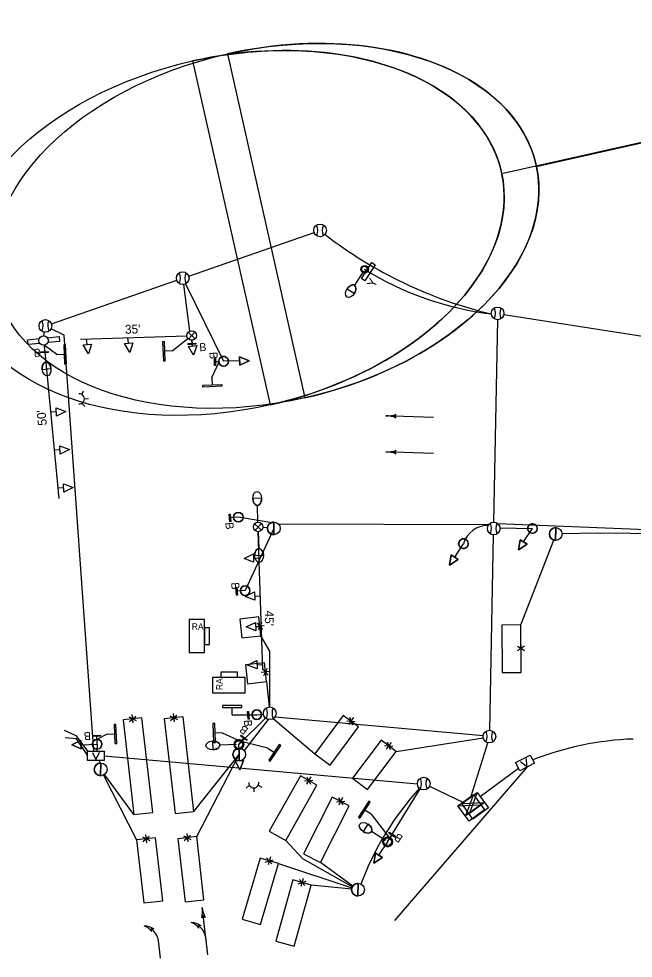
# Model space of a CAD drawing. Extents: x 596176 to 605330, y 332416 to 402398.
# Drawn here: x 604308.1 to 604501.7, y 339230.9 to 339526.7 of the extents above; entities that cross this region are included whole.
import ezdxf

# ---------------------------------------------------------------- set-up
doc = ezdxf.new("R2010")
doc.units = 0
for name, color, linetype in [('P_LTG', 7, 'Continuous'), ('P_SIG', 7, 'Continuous'), ('P_SIG_Bold', 7, 'Continuous'), ('P_SIG_Conduit', 7, 'Continuous'), ('P_SIG_IC', 7, 'Continuous'), ('P_SIG_Loops', 7, 'Continuous')]:
    doc.layers.add(name, color=color, linetype=linetype)

# ---------------------------------------------------------------- blocks, each defined once
blk = doc.blocks.new('_U317')
at = {"layer": 'P_LTG'}
for p, q in [((4.32, 25.12), (-4.14, 25.12)), ((0.05, 2.3), (0.05, 18.44))]:
    blk.add_line(p, q, dxfattribs=at)
blk.add_circle((0.05, 0.15), 3.68, dxfattribs=at)
blk.add_ellipse((0.09, 25.12), major_axis=(0, 6.65), ratio=0.636439, dxfattribs=at)
blk.add_ellipse((0.09, 25.12), major_axis=(0, 6.65), ratio=0.636439, start_param=1.570796, end_param=4.712389, dxfattribs=at)
blk = doc.blocks.new('_U318')
at = {"layer": 'P_LTG'}
for p, q in [((4.323, 25.117), (-4.138, 25.117)), ((0.048, 2.299), (0.048, 18.436))]:
    blk.add_line(p, q, dxfattribs=at)
blk.add_ellipse((0.092, 25.117), major_axis=(0, 6.647), ratio=0.636439, dxfattribs=at)
blk.add_ellipse((0.092, 25.117), major_axis=(0, 6.647), ratio=0.636439, start_param=1.570796, end_param=4.712389, dxfattribs=at)
blk = doc.blocks.new('_U226')
at = {"layer": 'P_SIG'}
blk.add_line((0.03, 6.11), (-0.03, -6.09), dxfattribs=at)
blk.add_lwpolyline([(-0.03, -6.09), (0.03, 6.11)], dxfattribs=at)
blk.add_circle((0, 0.01), 6.1, dxfattribs=at)
for start, end in [(89.70079, 180), (180, 269.70079)]:
    blk.add_arc((0, 0.01), 6.1, start, end, dxfattribs=at)
blk = doc.blocks.new('_U307')
at = {"layer": 'P_SIG_Loops'}
for p, q in [((0, 0), (0, -0.229)), ((0.517, -0.313), (0.624, -0.147)), ((0.627, -0.312), (0.518, -0.146)), ((0.467, -0.23), (0.671, -0.23))]:
    blk.add_line(p, q, dxfattribs=at)
blk.add_lwpolyline([(0, -0.229), (1.143, -0.229), (1.143, 0.229), (0, 0.229)], close=True, dxfattribs=at)
blk = doc.blocks.new('CONTROL CABINET_2')
at = {"layer": 'P_SIG'}
for p, q in [((-0.229, 0.305), (0.229, 0.305)), ((-0.229, -0.152), (-0.229, 0.305)), ((0.229, 0.305), (0.229, -0.152)), ((-0.229, 0.152), (0.229, 0.152)), ((-0.229, -0.152), (0.229, 0.152)), ((0.229, -0.152), (-0.229, 0.152)), ((0.229, -0.152), (-0.229, -0.152))]:
    blk.add_line(p, q, dxfattribs=at)
blk = doc.blocks.new('COMMUNICATION VAULT')
at = {"layer": 'P_SIG'}
for p in [(-1.61, 1.65), (1.56, 1.65)]:
    blk.add_line(p, (-0.03, -1.65), dxfattribs=at)
blk.add_lwpolyline([(-3.98, 2.22), (3.98, 2.22), (3.98, -2.22), (-3.98, -2.22)], close=True, dxfattribs=at)

msp = doc.modelspace()

# ---------------------------------------------------------------- linework, layer by layer
at = {"layer": 'P_SIG'}
for p, q in [((604416.11, 339444.89), (604419.37, 339449.93)), ((604420.38, 339449.28), (604417.11, 339444.24)), ((604419.37, 339449.93), (604420.38, 339449.28)), ((604417.11, 339444.24), (604416.11, 339444.89)), ((604329.66, 339424.14), (604329.45, 339425.9)), ((604342.7, 339424.56), (604342.49, 339426.32)), ((604356.38, 339422.11), (604361.38, 339426.04)), ((604362.84, 339423.71), (604362.63, 339425.47)), ((604362.63, 339425.46), (604362.67, 339424.47)), ((604316.05, 339423.89), (604316.14, 339421.91)), ((604320.12, 339420.97), (604316.11, 339423.9)), ((604356.38, 339422.11), (604353.98, 339422)), ((604320.12, 339420.97), (604322.52, 339421.08)), ((604368.88, 339413.72), (604371.27, 339418.66)), ((604371.1, 339418.7), (604370.1, 339418.68)), ((604377.67, 339418.96), (604372.61, 339418.86)), ((604368.88, 339413.72), (604368.99, 339411.32)), ((604327.93, 339408.43), (604328.5, 339409.52)), ((604328.77, 339407.07), (604330, 339407.09)), ((604327.95, 339405.64), (604328.85, 339404.67)), ((604319.9, 339402.91), (604318.13, 339402.86)), ((604438.73, 339401.16), (604426.17, 339401.61)), ((604321.06, 339390.95), (604319.29, 339390.89)), ((604438.73, 339389.81), (604426.17, 339390.25)), ((604322.22, 339378.98), (604320.45, 339378.92)), ((604377.27, 339369.77), (604374.78, 339369.56)), ((604388.46, 339368.23), (604388.44, 339364.23)), ((604467.17, 339361.96), (604469.95, 339366.19)), ((604445.44, 339357.18), (604448.21, 339361.41)), ((604382.04, 339356.89), (604383.81, 339356.94)), ((604379.42, 339346.64), (604376.92, 339346.44)), ((604382.43, 339344.89), (604384.2, 339344.95)), ((604382.73, 339335.32), (604384.5, 339335.37)), ((604383.1, 339323.28), (604384.87, 339323.34)), ((604375.28, 339307.56), (604375.28, 339309.96)), ((604375.28, 339307.56), (604383.08, 339307.56)), ((604383.08, 339307.56), (604380.59, 339307.36)), ((604332.78, 339298.24), (604332.64, 339300.73)), ((604335.97, 339301.38), (604332.69, 339299.78)), ((604335.97, 339301.38), (604338.37, 339301.5)), ((604372.22, 339301.9), (604369.82, 339301.79)), ((604372.22, 339301.9), (604378.2, 339299.14)), ((604377.45, 339298.14), (604378.95, 339300.14)), ((604327.72, 339298.12), (604332.78, 339298.26)), ((604377.6, 339293.11), (604377.45, 339298.16)), ((604386.61, 339296.99), (604378.2, 339299.14)), ((604331.31, 339295.67), (604332.35, 339293.5)), ((604333.39, 339295.67), (604332.35, 339293.5)), ((604377.55, 339297.03), (604377.53, 339293.03)), ((604386.61, 339296.99), (604388.62, 339295.68)), ((604333.9, 339292.32), (604333.88, 339288.32)), ((604380.75, 339285.33), (604379.78, 339284.43)), ((604383.54, 339285.35), (604384.63, 339284.78)), ((604382.18, 339284.51), (604382.2, 339283.28)), ((604446.48, 339278.91), (604451.34, 339282.43)), ((604451.34, 339282.43), (604448.82, 339275.67)), ((604451.34, 339282.43), (604454.86, 339277.57)), ((604419.11, 339276.2), (604417.09, 339277.5)), ((604446.48, 339278.91), (604453.68, 339279.19)), ((604450, 339274.06), (604446.48, 339278.91)), ((604453.68, 339279.19), (604448.82, 339275.67)), ((604454.86, 339277.57), (604450, 339274.06)), ((604419.11, 339276.2), (604425.02, 339268.54)), ((604421.56, 339263.29), (604424.34, 339267.52)), ((604424.32, 339267.5), (604425.71, 339269.58)), ((604414.98, 339254.42), (604414.96, 339250.42)), ((604367.62, 339231.98), (604366.17, 339244.46)), ((604364.87, 339240.35), (604364.59, 339241.22)), ((604365.55, 339241.09), (604364.59, 339241.22)), ((604350.03, 339239.26), (604349.75, 339240.12)), ((604350.71, 339239.99), (604349.75, 339240.12)), ((604352.78, 339230.88), (604352.13, 339236.43)), ((604367.62, 339231.98), (604366.98, 339237.53))]:
    msp.add_line(p, q, dxfattribs=at)
for points in [[(604419.37, 339449.93), (604420.38, 339449.28), (604417.11, 339444.24), (604416.11, 339444.89)], [(604330.01, 339421.21), (604328.36, 339423.99), (604330.97, 339424.3)], [(604343.05, 339421.62), (604341.4, 339424.41), (604344.01, 339424.72)], [(604354.25, 339419.05), (604353.97, 339425.04), (604353.37, 339425.01), (604353.65, 339419.02)], [(604361.47, 339424.41), (604363.87, 339424.52), (604363.89, 339424.2), (604361.49, 339424.09)], [(604314.94, 339421.86), (604317.34, 339421.97), (604317.35, 339421.64), (604314.95, 339421.53)], [(604322.24, 339424.03), (604322.52, 339418.03), (604323.12, 339418.06), (604322.84, 339424.06)], [(604363.19, 339420.77), (604361.53, 339423.55), (604364.14, 339423.86)], [(604370.08, 339419.88), (604370.12, 339417.48), (604369.8, 339417.48), (604369.76, 339419.88)], [(604366.03, 339411.32), (604372.03, 339411.59), (604372.05, 339410.99), (604366.06, 339410.72)], [(604322.86, 339403.01), (604319.94, 339401.6), (604319.86, 339404.23)], [(604324.02, 339391.04), (604321.1, 339389.63), (604321.02, 339392.26)], [(604325.17, 339379.07), (604322.26, 339377.66), (604322.17, 339380.29)], [(604374.68, 339370.76), (604374.88, 339368.37), (604374.56, 339368.34), (604374.36, 339370.73)], [(604379.09, 339356.79), (604382, 339358.2), (604382.08, 339355.57)], [(604376.83, 339347.63), (604377.02, 339345.24), (604376.7, 339345.22), (604376.5, 339347.61)], [(604379.47, 339344.8), (604382.39, 339346.21), (604382.47, 339343.58)], [(604366.6, 339327.17), (604366.6, 339337.52), (604361.78, 339337.52), (604361.78, 339327.17)], [(604379.78, 339335.22), (604382.69, 339336.63), (604382.78, 339334)], [(604368.23, 339334.89), (604366.63, 339334.89), (604366.63, 339329.62), (604368.23, 339329.62)], [(604380.15, 339323.19), (604383.06, 339324.6), (604383.15, 339321.97)], [(604371.72, 339320.95), (604371.72, 339319.35), (604376.99, 339319.35), (604376.99, 339320.95)], [(604379.44, 339319.32), (604369.09, 339319.32), (604369.09, 339314.5), (604379.44, 339314.5)], [(604372.32, 339309.83), (604378.32, 339309.83), (604378.32, 339310.43), (604372.32, 339310.43)], [(604380.49, 339308.55), (604380.69, 339306.16), (604380.36, 339306.13), (604380.16, 339308.53)], [(604338.1, 339304.44), (604338.38, 339298.45), (604338.98, 339298.48), (604338.7, 339304.47)], [(604370.09, 339298.84), (604369.82, 339304.84), (604369.22, 339304.81), (604369.49, 339298.81)], [(604333.84, 339300.8), (604331.44, 339300.67), (604331.42, 339300.99), (604333.82, 339301.13)], [(604379.91, 339299.43), (604377.99, 339300.86), (604378.18, 339301.12), (604380.1, 339299.69)], [(604390.12, 339298.23), (604386.84, 339293.2), (604387.34, 339292.88), (604390.62, 339297.9)], [(604329.76, 339296.04), (604334.97, 339296.04), (604334.97, 339293.13), (604329.76, 339293.13)], [(604415.6, 339274.94), (604418.86, 339279.98), (604418.35, 339280.31), (604415.1, 339275.27)], [(604426.71, 339268.92), (604424.71, 339270.25), (604424.89, 339270.52), (604426.89, 339269.19)]]:
    msp.add_lwpolyline(points, close=True, dxfattribs=at)
for points in [[(604380.63, 339419.02), (604377.7, 339417.64), (604377.64, 339420.28), (604380.63, 339419.02)], [(604377.7, 339417.64), (604380.63, 339419.02), (604377.64, 339420.28), (604377.7, 339417.64)], [(604426.98, 339402.08), (604426.17, 339401.61), (604426.95, 339401.08)], [(604426.98, 339390.72), (604426.17, 339390.25), (604426.95, 339389.73)], [(604388.44, 339364.23), (604388.46, 339368.23)], [(604465.55, 339359.49), (604466.07, 339362.68), (604468.27, 339361.24), (604465.55, 339359.49)], [(604466.07, 339362.68), (604465.55, 339359.49), (604468.27, 339361.24), (604466.07, 339362.68)], [(604443.82, 339354.7), (604444.33, 339357.9), (604446.54, 339356.46), (604443.82, 339354.7)], [(604444.33, 339357.9), (604443.82, 339354.7), (604446.54, 339356.46), (604444.33, 339357.9)], [(604324.76, 339298.03), (604327.68, 339299.43), (604327.76, 339296.8), (604324.76, 339298.03)], [(604327.68, 339299.43), (604324.76, 339298.03), (604327.76, 339296.8), (604327.68, 339299.43)], [(604377.53, 339293.03), (604377.55, 339297.03)], [(604333.88, 339288.32), (604333.9, 339292.32)], [(604377.69, 339290.15), (604376.28, 339293.07), (604378.92, 339293.15), (604377.69, 339290.15)], [(604376.28, 339293.07), (604377.69, 339290.15), (604378.92, 339293.15), (604376.28, 339293.07)], [(604419.94, 339260.82), (604420.46, 339264.01), (604422.66, 339262.57), (604419.94, 339260.82)], [(604420.46, 339264.01), (604419.94, 339260.82), (604422.66, 339262.57), (604420.46, 339264.01)], [(604414.96, 339250.42), (604414.98, 339254.42)], [(604366.76, 339243.73), (604366.17, 339244.46), (604365.77, 339243.61)]]:
    msp.add_lwpolyline(points, dxfattribs=at)
for centre, radius in [((604403.02, 339460.06), 2), ((604416.98, 339447.88), 0.9), ((604359.75, 339445.03), 2), ((604458.96, 339433.95), 2), ((604316.49, 339430), 2), ((604372.61, 339418.86), 1.52), ((604372.61, 339418.86), 1.52), ((604372.61, 339418.86), 1.52), ((604377.27, 339369.77), 1.52), ((604388.45, 339366.23), 2), ((604457.74, 339366.2), 2), ((604469.95, 339366.19), 1.52), ((604469.95, 339366.19), 1.52), ((604469.95, 339366.19), 1.52), ((604448.21, 339361.41), 1.52), ((604448.21, 339361.41), 1.52), ((604448.21, 339361.41), 1.52), ((604379.42, 339346.64), 1.52), ((604383.08, 339307.56), 1.52), ((604387.17, 339308.02), 2), ((604456.37, 339300.69), 2), ((604332.78, 339298.26), 1.52), ((604332.78, 339298.26), 1.52), ((604332.78, 339298.26), 1.52), ((604377.45, 339298.16), 1.52), ((604377.45, 339298.16), 1.52), ((604377.45, 339298.16), 1.52), ((604377.54, 339295.03), 2), ((604333.89, 339290.32), 2), ((604435.69, 339285.86), 2), ((604424.34, 339267.52), 1.52), ((604424.34, 339267.52), 1.52), ((604424.34, 339267.52), 1.52), ((604414.97, 339252.42), 2)]:
    msp.add_circle(centre, radius, dxfattribs=at)
for centre, radius, start, end in [((604397.95, 339460.09), 4.36, 336.6741, 22.5272), ((604408.09, 339460.1), 4.36, 157.5751, 203.4282), ((604354.68, 339445.06), 4.36, 336.6741, 22.5272), ((604364.82, 339445.07), 4.36, 157.5751, 203.4282), ((604453.89, 339433.98), 4.36, 336.6741, 22.5272), ((604464.03, 339433.99), 4.36, 157.5751, 203.4282), ((604311.42, 339430.03), 4.36, 336.6741, 22.5272), ((604321.56, 339430.04), 4.36, 157.5751, 203.4282), ((604372.61, 339418.86), 1.52, 1.2579, 181.2579), ((604372.61, 339418.86), 1.52, 181.2579, 1.2579), ((604327.2, 339407.03), 1.58, 263.3712, 98.8787), ((604424.14, 339412.17), 10.49, 267.9585, 285.7208), ((604423.39, 339391.21), 10.49, 70.1962, 87.9585), ((604424.14, 339400.82), 10.49, 267.9585, 285.7208), ((604423.39, 339379.86), 10.49, 70.1962, 87.9585), ((604377.27, 339369.77), 1.52, 0, 180), ((604377.27, 339369.77), 1.52, 180, 0), ((604388.45, 339366.23), 2, 89.7008, 180), ((604388.45, 339366.23), 2, 180, 269.7008), ((604452.67, 339366.23), 4.36, 336.6741, 22.5272), ((604462.81, 339366.24), 4.36, 157.5751, 203.4282), ((604469.95, 339366.19), 1.52, 56.8293, 236.8293), ((604469.95, 339366.19), 1.52, 236.8293, 56.8293), ((604448.21, 339361.41), 1.52, 56.8293, 236.8293), ((604448.21, 339361.41), 1.52, 236.8293, 56.8293), ((604379.42, 339346.64), 1.52, 0, 180), ((604379.42, 339346.64), 1.52, 180, 0), ((604383.08, 339307.56), 1.52, 0, 180), ((604382.1, 339308.06), 4.36, 336.6741, 22.5272), ((604392.24, 339308.07), 4.36, 157.5751, 203.4282), ((604383.08, 339307.56), 1.52, 180, 0), ((604451.3, 339300.73), 4.36, 336.6741, 22.5272), ((604461.44, 339300.74), 4.36, 157.5751, 203.4282), ((604332.78, 339298.26), 1.52, 1.8031, 181.8031), ((604332.78, 339298.26), 1.52, 181.8031, 1.8031), ((604377.45, 339298.16), 1.52, 91.8031, 271.8031), ((604377.45, 339298.16), 1.52, 271.8031, 91.8031), ((604377.54, 339295.03), 2, 89.7008, 180), ((604377.54, 339295.03), 2, 180, 269.7008), ((604333.89, 339290.32), 2, 89.7008, 180), ((604333.89, 339290.32), 2, 180, 269.7008), ((604382.14, 339286.08), 1.58, 173.3712, 8.8787), ((604430.62, 339285.9), 4.36, 336.6741, 22.5272), ((604440.76, 339285.9), 4.36, 157.5751, 203.4282), ((604424.34, 339267.52), 1.52, 56.8293, 236.8293), ((604424.34, 339267.52), 1.52, 236.8293, 56.8293), ((604414.97, 339252.42), 2, 89.7008, 180), ((604414.97, 339252.42), 2, 180, 269.7008), ((604355.48, 339245.64), 10.49, 348.8556, 6.6179), ((604376.32, 339248.06), 10.49, 186.6179, 204.3803), ((604345.91, 339236.18), 5.14, 36.7028, 71.3512), ((604347.27, 339234.99), 6.07, 55.4464, 87.3026), ((604360.75, 339237.28), 5.14, 36.7028, 71.3512), ((604362.11, 339236.09), 6.07, 55.4464, 87.3026), ((604361.28, 339236.46), 5.8, 10.5832, 55.1471), ((604346.43, 339235.37), 5.8, 10.5832, 55.1471)]:
    msp.add_arc(centre, radius, start, end, dxfattribs=at)
at = {"layer": 'P_SIG_Bold'}
for p, q in [((604361.46, 339427.99), (604363.65, 339425.94)), ((604363.58, 339428.06), (604361.53, 339425.87)), ((604327.58, 339425.84), (604361.06, 339426.92)), ((604316.05, 339423.89), (604320.71, 339375.62)), ((604382.4, 339367.72), (604384.59, 339365.66)), ((604382.47, 339365.6), (604384.52, 339367.78)), ((604384.94, 339321.71), (604383.55, 339365.19))]:
    msp.add_line(p, q, dxfattribs=at)
for points in [[(604314.68, 339424.51), (604311, 339424.16), (604310.85, 339425.65), (604314.54, 339426.01)], [(604317.12, 339426.26), (604320.81, 339426.61), (604320.95, 339425.12), (604317.27, 339424.76)]]:
    msp.add_lwpolyline(points, dxfattribs=at)
for centre in [(604362.56, 339426.96), (604315.9, 339425.39), (604383.5, 339366.69)]:
    msp.add_circle(centre, 1.5, dxfattribs=at)
at = {"layer": 'P_SIG_Conduit'}
for p, q in [((604360.01, 339443.04), (604361.88, 339428.3)), ((604360.64, 339443.23), (604372.61, 339418.86)), ((604458.92, 339431.95), (604457.68, 339368.2)), ((604316, 339426.88), (604316.17, 339428.02)), ((604388.46, 339367.86), (604377.27, 339369.77)), ((604388.45, 339366.23), (604379.42, 339346.64)), ((604459, 339367.75), (604540.44, 339364.59)), ((604457.61, 339364.2), (604456.41, 339302.69)), ((604377.45, 339298.19), (604385.87, 339306.5)), ((604386.65, 339306.09), (604379.11, 339296.27)), ((604383.08, 339307.56), (604385.19, 339307.74)), ((604332.78, 339298.26), (604332.71, 339296.04)), ((604450.64, 339281.93), (604455.87, 339298.75)), ((604334.97, 339294.58), (604433.69, 339285.83)), ((604333.56, 339293.13), (604333.65, 339292.31)), ((604437.5, 339285.01), (604448.02, 339280.03))]:
    msp.add_line(p, q, dxfattribs=at)
for points in [[(604361.64, 339445.68), (604401.13, 339459.4)], [(604318.38, 339430.65), (604357.87, 339444.37)], [(604460.93, 339433.64), (604522.77, 339423.92)], [(604331.69, 339296.04), (604322.39, 339427.06), (604318.27, 339429.09)], [(604386.46, 339366.41), (604384.99, 339366.55)], [(604389.89, 339367.62), (604456.16, 339367.43)], [(604459.73, 339366.42), (604469.95, 339366.19)], [(604632.71, 339363.27), (604490.54, 339364.68), (604479.27, 339364.49)], [(604388.85, 339306.94), (604454.4, 339301)], [(604322.43, 339302.71), (604326.09, 339301.02), (604329.69, 339296.04)], [(604329.69, 339294.79), (604326.31, 339299.98), (604322.71, 339300.31)], [(604424.32, 339267.5), (604434.61, 339284.18)]]:
    msp.add_lwpolyline(points, dxfattribs=at)
for centre, radius, start, end in [((604489.18, 339568.4), 138.44, 232.3316, 256.5435), ((604468.99, 339531.6), 98.57, 238.1454, 262.9944), ((604455.92, 339359.13), 8.04, 89.5224, 163.5022), ((604504.2, 339220.92), 94.4, 137.747, 159.353)]:
    msp.add_arc(centre, radius, start, end, dxfattribs=at)
at = {"layer": 'P_SIG_IC'}
msp.add_line((604426.58, 339242.71), (604468.43, 339291.17), dxfattribs=at)
msp.add_lwpolyline([(604453.47, 339281.83), (604465.51, 339290.72)], dxfattribs=at)
msp.add_arc((604504.95, 339205.09), 94.87, 91.963, 111.5856, dxfattribs=at)
at = {"layer": 'P_SIG_Loops'}
for p, q in [((604466.26, 339335.87), (604476.72, 339362.54)), ((604385.4, 339335.56), (604382.74, 339335.25)), ((604383.18, 339336.39), (604384.85, 339334.39)), ((604384.63, 339336.56), (604383.47, 339334.24)), ((604384.04, 339335.38), (604383.7, 339338.36)), ((604385.8, 339320.95), (604385.46, 339323.93)), ((604387.17, 339321.12), (604384.5, 339320.82)), ((604384.95, 339321.95), (604386.62, 339319.96)), ((604386.39, 339322.13), (604385.24, 339319.81)), ((604343.93, 339306.25), (604340.95, 339305.91)), ((604342.75, 339306.84), (604345.07, 339305.69)), ((604342.92, 339305.4), (604344.92, 339307.06)), ((604343.75, 339307.61), (604344.06, 339304.95)), ((604356.91, 339306.59), (604353.93, 339306.25)), ((604355.73, 339307.18), (604358.05, 339306.03)), ((604355.91, 339305.73), (604357.9, 339307.4)), ((604356.74, 339307.95), (604357.04, 339305.29)), ((604388.24, 339306.34), (604401.41, 339295.28)), ((604412.75, 339305.55), (604410.34, 339307.33)), ((604413.55, 339306.66), (604411.96, 339304.51)), ((604412.29, 339306.78), (604413.2, 339304.36)), ((604411.44, 339305.61), (604414.03, 339305.47)), ((604427.04, 339295.94), (604454.42, 339300.25)), ((604424.65, 339297.76), (604422.26, 339299.57)), ((604423.34, 339297.83), (604425.93, 339297.66)), ((604425.47, 339298.86), (604423.85, 339296.73)), ((604424.21, 339299), (604425.09, 339296.56)), ((604363.29, 339277.12), (604377.54, 339295.03)), ((604364.17, 339269.17), (604377.54, 339295.03)), ((604334.8, 339288.54), (604345.23, 339268.15)), ((604344.35, 339276.1), (604335.07, 339288.71)), ((604399.43, 339286.83), (604396.81, 339288.3)), ((604398.12, 339286.72), (604400.71, 339286.91)), ((604400.08, 339288.03), (604398.77, 339285.7)), ((604398.82, 339288), (604400.02, 339285.7)), ((604409.52, 339280.24), (604406.84, 339281.59)), ((604408.21, 339280.08), (604410.8, 339280.38)), ((604408.86, 339281.38), (604410.16, 339279.14)), ((604410.12, 339281.47), (604408.92, 339279.08)), ((604348.21, 339268.49), (604345.23, 339268.15)), ((604347.03, 339269.08), (604349.35, 339267.93)), ((604347.2, 339267.64), (604349.2, 339269.31)), ((604348.03, 339269.85), (604348.34, 339267.19)), ((604361.19, 339268.83), (604358.21, 339268.49)), ((604360.01, 339269.42), (604362.33, 339268.27)), ((604360.19, 339267.98), (604362.19, 339269.64)), ((604361.02, 339270.19), (604361.32, 339267.53)), ((604387.01, 339261.51), (604384.13, 339262.36)), ((604385.75, 339261.12), (604388.24, 339261.87)), ((604386.15, 339262.51), (604387.84, 339260.55)), ((604387.38, 339262.83), (604386.62, 339260.26)), ((604413.36, 339253.6), (604403.18, 339261.04)), ((604396.5, 339255.7), (604398.21, 339253.75)), ((604397.72, 339256.03), (604397, 339253.45)), ((604397.37, 339254.71), (604394.48, 339255.51)), ((604396.12, 339254.29), (604398.6, 339255.09)), ((604412.98, 339252.62), (604400.26, 339253.9))]:
    msp.add_line(p, q, dxfattribs=at)
for points in [[(604383.7, 339338.36), (604377.73, 339337.68), (604378.42, 339331.72), (604384.38, 339332.4)], [(604385.46, 339323.93), (604379.5, 339323.25), (604380.18, 339317.29), (604386.14, 339317.97)], [(604340.95, 339305.91), (604344.35, 339276.1), (604350.31, 339276.78), (604346.91, 339306.59)], [(604353.93, 339306.25), (604357.33, 339276.44), (604363.29, 339277.12), (604359.89, 339306.93)], [(604410.34, 339307.33), (604401.41, 339295.28), (604406.23, 339291.71), (604415.16, 339303.76)], [(604422.26, 339299.57), (604413.2, 339287.61), (604417.98, 339283.99), (604427.04, 339295.94)], [(604396.81, 339288.3), (604387.01, 339270.86), (604392.24, 339267.92), (604402.04, 339285.36)], [(604406.84, 339281.59), (604397.82, 339263.74), (604403.18, 339261.04), (604412.2, 339278.89)], [(604345.23, 339268.15), (604347.49, 339248.28), (604353.46, 339248.96), (604351.19, 339268.83)], [(604358.21, 339268.49), (604360.48, 339248.62), (604366.44, 339249.3), (604364.17, 339269.17)], [(604384.13, 339262.36), (604378.48, 339243.18), (604384.23, 339241.48), (604389.89, 339260.66)], [(604394.48, 339255.51), (604389.09, 339236.25), (604394.87, 339234.64), (604400.26, 339253.9)]]:
    msp.add_lwpolyline(points, close=True, dxfattribs=at)
for points in [[(604387.17, 339310.02), (604387.16, 339327.57), (604384.38, 339332.4)], [(604386.14, 339317.97), (604386.96, 339310.01)], [(604392.24, 339267.92), (604397.46, 339262.3), (604413.23, 339253.4)], [(604389.89, 339260.66), (604413.07, 339253.04)]]:
    msp.add_lwpolyline(points, dxfattribs=at)

# ---------------------------------------------------------------- block references
at = {"layer": 'P_SIG'}
for name, p, xscale, yscale, rotation in [('_U318', (604707.83, 339532.72), 13.123333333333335, 13.123333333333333, 102.6891845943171), ('_U318', (604696.9, 339530.5), 13.123333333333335, 13.123333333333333, 102.6891845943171), ('_U317', (604417.13, 339447.88), 0.32808333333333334, 0.32808333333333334, 147.58059147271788), ('_U318', (604315.98, 339424.64), 0.32808333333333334, 0.32808333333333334, -173.71516295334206), ('_U318', (604383.46, 339367.43), 0.32808333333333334, 0.3280833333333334, 1.956191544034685), ('_U318', (604383.54, 339365.94), 0.3280833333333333, 0.32808333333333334, -178.0438084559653), ('_U317', (604377.45, 339298.16), 0.32808333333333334, 0.32808333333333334, 91.9352759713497), ('CONTROL CABINET_2', (604451.28, 339279.72), 13.123333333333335, 13.123333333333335, -143.99007179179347), ('_U317', (604424.32, 339267.5), 0.3280833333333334, 0.32808333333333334, 57.58059147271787)]:
    msp.add_blockref(name, p, dxfattribs=dict(at, xscale=xscale, yscale=yscale, rotation=rotation))
at = {"layer": 'P_SIG_Conduit', "xscale": 0.32808333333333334, "yscale": 0.32808333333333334}
msp.add_blockref('_U226', (604477.27, 339364.46), dxfattribs=at)
at = {"layer": 'P_SIG_IC', "xscale": 0.6561666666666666, "yscale": 0.6561666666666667, "rotation": 27.021017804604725}
msp.add_blockref('COMMUNICATION VAULT', (604467.59, 339292.37), dxfattribs=at)
at = {"layer": 'P_SIG_Loops', "xscale": 13.123333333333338, "yscale": 13.123333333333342, "rotation": 90.59788262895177}
msp.add_blockref('_U307', (604463.42, 339320.84), dxfattribs=at)

# ---------------------------------------------------------------- texts
at = {"layer": 'P_SIG'}
for s, height, rotation, p in [('Y', 2.8, 64.8732, (604420.21, 339441.89)), ('B', 2.52, 2.6556, (604365.02, 339422.01)), ('B', 2.52, 2.6556, (604312.88, 339420.23)), ('B', 2.52, 272.6556, (604368.16, 339421.75)), ("50'", 2.8, 95.5203, (604316.95, 339398.75)), ('B', 2.52, 274.7289, (604373.17, 339368.06)), ('B', 2.52, 274.7289, (604374.97, 339349.13)), ('RA', 2, 360, (604362.59, 339334.33)), ('RA', 2, 90, (604372.28, 339315.31)), ('B', 2.52, 143.3114, (604380.61, 339303.07)), ('B', 2.52, 274.7289, (604378.97, 339305.85)), ('B', 2.52, 183.2956, (604330.73, 339302.16)), ('B', 2.52, 146.3763, (604429.34, 339269.17))]:
    msp.add_text(s, height=height, rotation=rotation, dxfattribs=at).set_placement(p)
at = {"layer": 'P_SIG_Bold'}
for s, rotation, p in [("35'", 1.8373, (604341.57, 339427.5)), ("45'", 270, (604385.63, 339340.36))]:
    msp.add_text(s, height=2.8, rotation=rotation, dxfattribs=at).set_placement(p)

doc.saveas('drawing.dxf')
